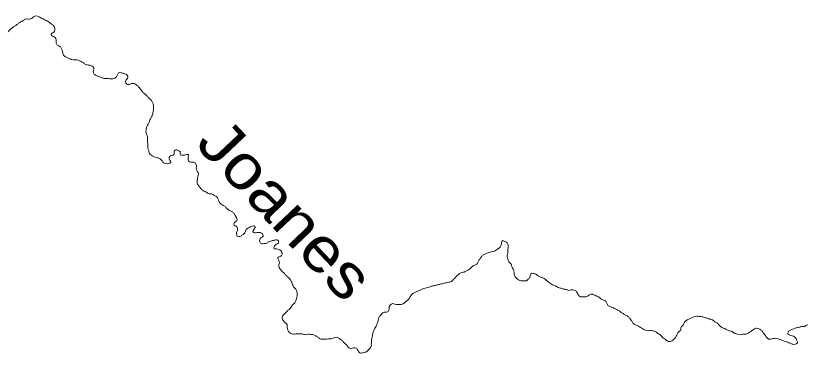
# Model space of a CAD drawing. Extents: x 854879 to 917879, y 8541948 to 8631048.
# Drawn here: x 880862 to 887947, y 8603519 to 8606565 of the extents above; entities that cross this region are included whole.
import ezdxf

# ---------------------------------------------------------------- set-up
doc = ezdxf.new("R2010")
doc.units = 0
doc.header["$LTSCALE"] = 160
doc.layers.add('1', color=7, linetype='Continuous', lineweight=13)
doc.layers.add('3', color=7, linetype='Continuous', lineweight=13)

msp = doc.modelspace()

# ---------------------------------------------------------------- linework, layer by layer
at = {"layer": '3'}
for points in [[(880861.8, 8606477.6), (880882.8, 8606492), (880906.5, 8606508.9), (880929.9, 8606520.7), (880950.9, 8606535.1), (880973.8, 8606534.1), (881012.6, 8606545.3), (881033.7, 8606562.2), (881059.1, 8606561.2), (881086.6, 8606547.3), (881109.1, 8606536.2), (881129.1, 8606525.2), (881149.1, 8606516.7), (881176.3, 8606495.2), (881196.2, 8606481.6), (881213.2, 8606460.6), (881214.7, 8606435), (881203.7, 8606415.1), (881185.4, 8606405.6), (881187.1, 8606385.2), (881209.6, 8606374.1), (881224.3, 8606358.2), (881228.4, 8606335.1), (881232.3, 8606304.3), (881259.7, 8606287.9), (881276.7, 8606266.8), (881285.8, 8606241), (881289.8, 8606215.3), (881314.5, 8606193.9), (881339.5, 8606182.7), (881369.6, 8606168.7), (881389.9, 8606167.9), (881425.5, 8606163.9), (881453.1, 8606152.5), (881473, 8606141.5), (881492.8, 8606125.4), (881523.1, 8606119.1), (881553.4, 8606110.2), (881568, 8606094.3), (881564.6, 8606071.5), (881563.7, 8606051.1), (881583.3, 8606029.9), (881605.8, 8606018.8), (881635.9, 8606007.4), (881661.1, 8605998.7), (881684, 8605997.8), (881709.4, 8605996.7), (881729.8, 8605995.8), (881763.4, 8606007.2), (881776.9, 8606024.5), (881790.7, 8606049.4), (881813.7, 8606051), (881838.9, 8606042.3), (881868.9, 8606028.3), (881873.2, 8606007.8), (881856.7, 8605980.4), (881855.9, 8605960.1), (881870.6, 8605944.2), (881896.2, 8605948.2), (881919.5, 8605954.9), (881944.6, 8605946.2), (881961.9, 8605932.8), (881979, 8605914.2), (881993.6, 8605895.8), (882005.6, 8605877.4), (882025.3, 8605861.3), (882045, 8605842.7), (882064.5, 8605821.5), (882081.7, 8605805.5), (882098.6, 8605781.9), (882105.2, 8605756.1), (882106.6, 8605728), (882103, 8605702.7), (882099.4, 8605677.4), (882085.4, 8605647.4), (882074.3, 8605624.9), (882063, 8605597.3), (882051.9, 8605577.4), (882043.4, 8605554.8), (882039.9, 8605532.1), (882038.8, 8605506.6), (882048.2, 8605485.8), (882052.2, 8605460.2), (882051.3, 8605437.3), (882055.2, 8605409.1), (882056.3, 8605373.4), (882062.8, 8605345.1), (882069.5, 8605321.9), (882086.7, 8605305.9), (882111.7, 8605292.1), (882134.4, 8605286.1)], [(880861.8, 8606477.6), (880882.8, 8606492), (880906.5, 8606508.9), (880929.9, 8606520.7), (880950.9, 8606535.1), (880973.8, 8606534.1), (881012.6, 8606545.3), (881033.7, 8606562.2), (881059.1, 8606561.2), (881086.6, 8606547.3), (881109.1, 8606536.2), (881129.1, 8606525.2), (881149.1, 8606516.7), (881176.3, 8606495.2), (881196.2, 8606481.6), (881213.2, 8606460.6), (881214.7, 8606435), (881203.7, 8606415.1), (881185.4, 8606405.6), (881187.1, 8606385.2), (881209.6, 8606374.1), (881224.3, 8606358.2), (881228.4, 8606335.1), (881232.3, 8606304.3), (881259.7, 8606287.9), (881276.7, 8606266.8), (881285.8, 8606241), (881289.8, 8606215.3), (881314.5, 8606193.9), (881339.5, 8606182.7), (881369.6, 8606168.7), (881389.9, 8606167.9), (881425.5, 8606163.9), (881453.1, 8606152.5), (881473, 8606141.5), (881492.8, 8606125.4), (881523.1, 8606119.1), (881553.4, 8606110.2), (881568, 8606094.3), (881564.6, 8606071.5), (881563.7, 8606051.1), (881583.3, 8606029.9), (881605.8, 8606018.8), (881635.9, 8606007.4), (881661.1, 8605998.7), (881684, 8605997.8), (881709.4, 8605996.7), (881729.8, 8605995.8), (881763.4, 8606007.2), (881776.9, 8606024.5), (881790.7, 8606049.4), (881813.7, 8606051), (881838.9, 8606042.3), (881868.9, 8606028.3), (881873.2, 8606007.8), (881856.7, 8605980.4), (881855.9, 8605960.1), (881870.6, 8605944.2), (881896.2, 8605948.2), (881919.5, 8605954.9), (881944.6, 8605946.2), (881961.9, 8605932.8), (881979, 8605914.2), (881993.6, 8605895.8), (882005.6, 8605877.4), (882025.3, 8605861.3), (882045, 8605842.7), (882064.5, 8605821.5), (882081.7, 8605805.5), (882098.6, 8605781.9), (882105.2, 8605756.1), (882106.6, 8605728), (882103, 8605702.7), (882099.4, 8605677.4), (882085.4, 8605647.4), (882074.3, 8605624.9), (882063, 8605597.3), (882051.9, 8605577.4), (882043.4, 8605554.8), (882039.9, 8605532.1), (882038.8, 8605506.6), (882048.2, 8605485.8), (882052.2, 8605460.2), (882051.3, 8605437.3), (882055.2, 8605409.1), (882056.3, 8605373.4), (882062.8, 8605345.1), (882069.5, 8605321.9), (882086.7, 8605305.9), (882111.7, 8605292.1), (882134.4, 8605286.1)], [(880371.3, 8606429.1), (880426.5, 8606437), (880445.3, 8606459.2), (880461.5, 8606481.4), (880482.6, 8606498.4), (880508.7, 8606512.6), (880532.1, 8606524.4), (880563.3, 8606538.4), (880583.6, 8606535), (880603.6, 8606526.5), (880623.4, 8606510.4), (880645.8, 8606496.8), (880662.7, 8606473.1), (880679.7, 8606452), (880691.5, 8606428.6), (880708.2, 8606402.4), (880730.5, 8606386.2), (880761.4, 8606392.6), (880780, 8606409.7), (880795.9, 8606424.3), (880814.5, 8606443.9), (880838.3, 8606463.3), (880861.8, 8606477.6)], [(880371.3, 8606429.1), (880426.5, 8606437), (880445.3, 8606459.2), (880461.5, 8606481.4), (880482.6, 8606498.4), (880508.7, 8606512.6), (880532.1, 8606524.4), (880563.3, 8606538.4), (880583.6, 8606535), (880603.6, 8606526.5), (880623.4, 8606510.4), (880645.8, 8606496.8), (880662.7, 8606473.1), (880679.7, 8606452), (880691.5, 8606428.6), (880708.2, 8606402.4), (880730.5, 8606386.2), (880761.4, 8606392.6), (880780, 8606409.7), (880795.9, 8606424.3), (880814.5, 8606443.9), (880838.3, 8606463.3), (880861.8, 8606477.6)], [(882134.4, 8605286.1), (882159.5, 8605277.4), (882179.3, 8605261.3), (882196.2, 8605237.7), (882216.3, 8605231.8), (882241.8, 8605230.7), (882262.7, 8605242.6), (882250.9, 8605266), (882252.1, 8605294), (882272.8, 8605303.3), (882291.1, 8605312.7), (882292, 8605335.6), (882308.1, 8605355.3), (882328.3, 8605349.4), (882348.2, 8605335.9), (882347.3, 8605315.5), (882375, 8605306.7), (882398.2, 8605310.9), (882423.6, 8605309.8), (882420.2, 8605289.6), (882419.3, 8605266.7), (882431.2, 8605245.8), (882456.7, 8605244.7), (882479.4, 8605238.7), (882493.6, 8605212.6), (882492.7, 8605189.8), (882496.9, 8605169.2), (882511.3, 8605145.7), (882510.3, 8605122.8), (882504.3, 8605100.1), (882500.8, 8605077.3), (882499.8, 8605051.9), (882514.2, 8605030.9), (882533.7, 8605007.2), (882555.7, 8604985.9), (882575.8, 8604977.4), (882608.2, 8604958.2), (882628.6, 8604957.4), (882653.5, 8604943.6), (882676, 8604932.5), (882688, 8604914.1), (882697.2, 8604890.8), (882709.2, 8604872.5), (882726.6, 8604859), (882746.5, 8604848), (882766.2, 8604829.4), (882788.3, 8604810.6), (882810.8, 8604799.5), (882830.6, 8604783.4), (882845, 8604762.4), (882854.5, 8604744.2), (882858.5, 8604716), (882834.7, 8604696.6), (882833.9, 8604676.2), (882853.8, 8604665.2), (882865.5, 8604639.3), (882859.5, 8604616.6), (882856.1, 8604596.3), (882867.9, 8604572.9), (882893.6, 8604577), (882914.6, 8604591.4), (882933.2, 8604611), (882939.2, 8604631.1), (882962.9, 8604650.5), (882986.3, 8604662.3), (883007, 8604669.1), (883024.4, 8604658.2), (883013.3, 8604635.7), (883002.4, 8604618.3), (883019.7, 8604604.9), (883040.3, 8604609.1), (883070.8, 8604607.8), (883090.8, 8604596.8), (883095.1, 8604576.3), (883076.6, 8604561.8), (883065.7, 8604544.4), (883064.9, 8604524), (883084.6, 8604507.9), (883105.1, 8604509.6), (883128.2, 8604513.8), (883151.8, 8604528.1), (883175, 8604534.8), (883203.3, 8604541.2), (883233.7, 8604534.9), (883235.4, 8604514.4), (883214.5, 8604502.5), (883198.5, 8604485.4), (883195, 8604462.6), (883217.9, 8604461.6), (883240.6, 8604455.6), (883260.5, 8604442)], [(882134.4, 8605286.1), (882159.5, 8605277.4), (882179.3, 8605261.3), (882196.2, 8605237.7), (882216.3, 8605231.8), (882241.8, 8605230.7), (882262.7, 8605242.6), (882250.9, 8605266), (882252.1, 8605294), (882272.8, 8605303.3), (882291.1, 8605312.7), (882292, 8605335.6), (882308.1, 8605355.3), (882328.3, 8605349.4), (882348.2, 8605335.9), (882347.3, 8605315.5), (882375, 8605306.7), (882398.2, 8605310.9), (882423.6, 8605309.8), (882420.2, 8605289.6), (882419.3, 8605266.7), (882431.2, 8605245.8), (882456.7, 8605244.7), (882479.4, 8605238.7), (882493.6, 8605212.6), (882492.7, 8605189.8), (882496.9, 8605169.2), (882511.3, 8605145.7), (882510.3, 8605122.8), (882504.3, 8605100.1), (882500.8, 8605077.3), (882499.8, 8605051.9), (882514.2, 8605030.9), (882533.7, 8605007.2), (882555.7, 8604985.9), (882575.8, 8604977.4), (882608.2, 8604958.2), (882628.6, 8604957.4), (882653.5, 8604943.6), (882676, 8604932.5), (882688, 8604914.1), (882697.2, 8604890.8), (882709.2, 8604872.5), (882726.6, 8604859), (882746.5, 8604848), (882766.2, 8604829.4), (882788.3, 8604810.6), (882810.8, 8604799.5), (882830.6, 8604783.4), (882845, 8604762.4), (882854.5, 8604744.2), (882858.5, 8604716), (882834.7, 8604696.6), (882833.9, 8604676.2), (882853.8, 8604665.2), (882865.5, 8604639.3), (882859.5, 8604616.6), (882856.1, 8604596.3), (882867.9, 8604572.9), (882893.6, 8604577), (882914.6, 8604591.4), (882933.2, 8604611), (882939.2, 8604631.1), (882962.9, 8604650.5), (882986.3, 8604662.3), (883007, 8604669.1), (883024.4, 8604658.2), (883013.3, 8604635.7), (883002.4, 8604618.3), (883019.7, 8604604.9), (883040.3, 8604609.1), (883070.8, 8604607.8), (883090.8, 8604596.8), (883095.1, 8604576.3), (883076.6, 8604561.8), (883065.7, 8604544.4), (883064.9, 8604524), (883084.6, 8604507.9), (883105.1, 8604509.6), (883128.2, 8604513.8), (883151.8, 8604528.1), (883175, 8604534.8), (883203.3, 8604541.2), (883233.7, 8604534.9), (883235.4, 8604514.4), (883214.5, 8604502.5), (883198.5, 8604485.4), (883195, 8604462.6), (883217.9, 8604461.6), (883240.6, 8604455.6), (883260.5, 8604442)], [(884400.4, 8603997.4), (884413.8, 8604014.7), (884430.2, 8604039.5), (884448.8, 8604059.1), (884472.3, 8604070.9), (884498.2, 8604082.6), (884519, 8604091.9), (884545, 8604103.6), (884570.8, 8604110.1), (884594, 8604116.8), (884622.5, 8604125.8), (884650.8, 8604132.3), (884679.1, 8604138.8), (884712.6, 8604147.6), (884751.3, 8604156.2), (884771.8, 8604160.4), (884792.4, 8604164.7), (884813.6, 8604184.2), (884834.9, 8604206.2), (884856.2, 8604228.3), (884882.5, 8604245), (884921.2, 8604256.2), (884944.7, 8604270.5), (884963.1, 8604282.5), (884981.6, 8604299.5), (885007.7, 8604313.7), (885028.7, 8604328.2), (885039.8, 8604350.6), (885056.2, 8604375.4), (885072.3, 8604395.1), (885090.8, 8604412.2), (885116.7, 8604421.3), (885137.4, 8604428.1), (885158.1, 8604434.9), (885183.9, 8604441.5), (885202.2, 8604453.5), (885225.8, 8604467.8), (885241.9, 8604487.5), (885247.8, 8604507.6), (885256.6, 8604535.3), (885279.3, 8604529.3), (885304, 8604510.4), (885308.1, 8604484.8), (885306.9, 8604456.8), (885306, 8604433.9), (885302.6, 8604413.7), (885299.2, 8604393.4), (885305.8, 8604367.7), (885320, 8604339), (885334.6, 8604323.2), (885343.8, 8604297.3), (885353.2, 8604279.1), (885362.2, 8604250.7), (885366.2, 8604222.5), (885383, 8604196.3), (885402.8, 8604182.7), (885422.9, 8604174.3), (885443.3, 8604173.4), (885468.7, 8604172.4), (885489.7, 8604186.8), (885505.8, 8604206.5), (885512.2, 8604236.8), (885537.9, 8604240.8), (885562.9, 8604229.6), (885585.3, 8604216), (885610.4, 8604204.7), (885632.9, 8604193.6), (885650.3, 8604182.7), (885672.4, 8604161.4), (885689.8, 8604150.5), (885709.6, 8604136.9), (885729.8, 8604131), (885759.7, 8604114.5), (885779.9, 8604108.5), (885805, 8604099.9), (885835.4, 8604093.5), (885858, 8604084.9), (885878.7, 8604091.7), (885909, 8604085.4), (885931.3, 8604069.2), (885940.7, 8604048.4), (885962.9, 8604029.6), (885983.2, 8604028.8), (886019.1, 8604032.4), (886042.7, 8604046.7), (886065.9, 8604053.4), (886091, 8604044.7), (886111, 8604033.7), (886131.1, 8604025.2), (886148.2, 8604009.2), (886180.3, 8603996.9)], [(884400.4, 8603997.4), (884413.8, 8604014.7), (884430.2, 8604039.5), (884448.8, 8604059.1), (884472.3, 8604070.9), (884498.2, 8604082.6), (884519, 8604091.9), (884545, 8604103.6), (884570.8, 8604110.1), (884594, 8604116.8), (884622.5, 8604125.8), (884650.8, 8604132.3), (884679.1, 8604138.8), (884712.6, 8604147.6), (884751.3, 8604156.2), (884771.8, 8604160.4), (884792.4, 8604164.7), (884813.6, 8604184.2), (884834.9, 8604206.2), (884856.2, 8604228.3), (884882.5, 8604245), (884921.2, 8604256.2), (884944.7, 8604270.5), (884963.1, 8604282.5), (884981.6, 8604299.5), (885007.7, 8604313.7), (885028.7, 8604328.2), (885039.8, 8604350.6), (885056.2, 8604375.4), (885072.3, 8604395.1), (885090.8, 8604412.2), (885116.7, 8604421.3), (885137.4, 8604428.1), (885158.1, 8604434.9), (885183.9, 8604441.5), (885202.2, 8604453.5), (885225.8, 8604467.8), (885241.9, 8604487.5), (885247.8, 8604507.6), (885256.6, 8604535.3), (885279.3, 8604529.3), (885304, 8604510.4), (885308.1, 8604484.8), (885306.9, 8604456.8), (885306, 8604433.9), (885302.6, 8604413.7), (885299.2, 8604393.4), (885305.8, 8604367.7), (885320, 8604339), (885334.6, 8604323.2), (885343.8, 8604297.3), (885353.2, 8604279.1), (885362.2, 8604250.7), (885366.2, 8604222.5), (885383, 8604196.3), (885402.8, 8604182.7), (885422.9, 8604174.3), (885443.3, 8604173.4), (885468.7, 8604172.4), (885489.7, 8604186.8), (885505.8, 8604206.5), (885512.2, 8604236.8), (885537.9, 8604240.8), (885562.9, 8604229.6), (885585.3, 8604216), (885610.4, 8604204.7), (885632.9, 8604193.6), (885650.3, 8604182.7), (885672.4, 8604161.4), (885689.8, 8604150.5), (885709.6, 8604136.9), (885729.8, 8604131), (885759.7, 8604114.5), (885779.9, 8604108.5), (885805, 8604099.9), (885835.4, 8604093.5), (885858, 8604084.9), (885878.7, 8604091.7), (885909, 8604085.4), (885931.3, 8604069.2), (885940.7, 8604048.4), (885962.9, 8604029.6), (885983.2, 8604028.8), (886019.1, 8604032.4), (886042.7, 8604046.7), (886065.9, 8604053.4), (886091, 8604044.7), (886111, 8604033.7), (886131.1, 8604025.2), (886148.2, 8604009.2), (886180.3, 8603996.9)], [(883260.5, 8604442), (883267.3, 8604421.4), (883256.1, 8604396.4), (883230, 8604382.2), (883241.3, 8604348.6), (883240.4, 8604325.7), (883237, 8604305.4), (883246.4, 8604284.7), (883263.4, 8604263.6), (883280.6, 8604247.6), (883297.7, 8604229), (883317.3, 8604210.4), (883334.5, 8604194.4), (883348.8, 8604170.9), (883358.2, 8604150.1), (883367.4, 8604126.8), (883382, 8604108.3), (883396.4, 8604087.4), (883403, 8604061.6), (883402.1, 8604038.7), (883396, 8604013.5), (883390, 8603993.3), (883378.9, 8603970.9), (883357.7, 8603951.4), (883346.7, 8603931.4), (883320.2, 8603907.1), (883301.5, 8603887.4), (883280.3, 8603867.9), (883268.9, 8603837.8), (883278.1, 8603814.5), (883297.7, 8603793.3), (883312.2, 8603774.9), (883313.9, 8603754.4), (883318, 8603728.8), (883337.4, 8603705.1), (883354.8, 8603694.2), (883377.7, 8603693.2), (883403.3, 8603694.7), (883428.9, 8603696.2), (883449.2, 8603695.3), (883477, 8603686.6), (883502.6, 8603690.6), (883523, 8603689.8), (883553.5, 8603685.9), (883576, 8603674.8), (883595.7, 8603658.7), (883618.2, 8603647.6), (883648.8, 8603646.3), (883671.8, 8603647.9), (883697.4, 8603649.4), (883723, 8603653.4), (883743.8, 8603662.8), (883766.7, 8603661.8), (883791.7, 8603648.1), (883809, 8603634.6), (883826.1, 8603616.1), (883848.2, 8603594.8), (883867.6, 8603571), (883887.7, 8603562.6), (883913.5, 8603569.1), (883936.3, 8603565.7), (883953.3, 8603544.6), (883970.2, 8603523.5), (884000.9, 8603524.8), (884029.3, 8603533.8), (884053.2, 8603555.7), (884072.2, 8603583), (884073, 8603603.3), (884073.8, 8603623.7), (884074.7, 8603644), (884080.6, 8603664.1), (884084.1, 8603686.9), (884093, 8603717.1), (884104.3, 8603744.7), (884117.9, 8603764.5), (884126.7, 8603792.2), (884135.3, 8603817.3), (884141.5, 8603842.5), (884157.6, 8603862.2), (884171.1, 8603879.5), (884197.1, 8603891.2), (884220.1, 8603892.8), (884233.7, 8603915.1), (884234.8, 8603940.6), (884245.7, 8603958), (884276.7, 8603966.9), (884296.8, 8603960.9), (884322.3, 8603959.9), (884355.6, 8603963.6), (884376.6, 8603978), (884400.4, 8603997.4)], [(883260.5, 8604442), (883267.3, 8604421.4), (883256.1, 8604396.4), (883230, 8604382.2), (883241.3, 8604348.6), (883240.4, 8604325.7), (883237, 8604305.4), (883246.4, 8604284.7), (883263.4, 8604263.6), (883280.6, 8604247.6), (883297.7, 8604229), (883317.3, 8604210.4), (883334.5, 8604194.4), (883348.8, 8604170.9), (883358.2, 8604150.1), (883367.4, 8604126.8), (883382, 8604108.3), (883396.4, 8604087.4), (883403, 8604061.6), (883402.1, 8604038.7), (883396, 8604013.5), (883390, 8603993.3), (883378.9, 8603970.9), (883357.7, 8603951.4), (883346.7, 8603931.4), (883320.2, 8603907.1), (883301.5, 8603887.4), (883280.3, 8603867.9), (883268.9, 8603837.8), (883278.1, 8603814.5), (883297.7, 8603793.3), (883312.2, 8603774.9), (883313.9, 8603754.4), (883318, 8603728.8), (883337.4, 8603705.1), (883354.8, 8603694.2), (883377.7, 8603693.2), (883403.3, 8603694.7), (883428.9, 8603696.2), (883449.2, 8603695.3), (883477, 8603686.6), (883502.6, 8603690.6), (883523, 8603689.8), (883553.5, 8603685.9), (883576, 8603674.8), (883595.7, 8603658.7), (883618.2, 8603647.6), (883648.8, 8603646.3), (883671.8, 8603647.9), (883697.4, 8603649.4), (883723, 8603653.4), (883743.8, 8603662.8), (883766.7, 8603661.8), (883791.7, 8603648.1), (883809, 8603634.6), (883826.1, 8603616.1), (883848.2, 8603594.8), (883867.6, 8603571), (883887.7, 8603562.6), (883913.5, 8603569.1), (883936.3, 8603565.7), (883953.3, 8603544.6), (883970.2, 8603523.5), (884000.9, 8603524.8), (884029.3, 8603533.8), (884053.2, 8603555.7), (884072.2, 8603583), (884073, 8603603.3), (884073.8, 8603623.7), (884074.7, 8603644), (884080.6, 8603664.1), (884084.1, 8603686.9), (884093, 8603717.1), (884104.3, 8603744.7), (884117.9, 8603764.5), (884126.7, 8603792.2), (884135.3, 8603817.3), (884141.5, 8603842.5), (884157.6, 8603862.2), (884171.1, 8603879.5), (884197.1, 8603891.2), (884220.1, 8603892.8), (884233.7, 8603915.1), (884234.8, 8603940.6), (884245.7, 8603958), (884276.7, 8603966.9), (884296.8, 8603960.9), (884322.3, 8603959.9), (884355.6, 8603963.6), (884376.6, 8603978), (884400.4, 8603997.4)], [(887833.8, 8603621), (887853.8, 8603610), (887878.9, 8603601.3), (887899.3, 8603600.5), (887920.2, 8603612.4), (887916, 8603635.5), (887904.2, 8603658.9), (887884.4, 8603672.5), (887861.8, 8603681), (887834.2, 8603692.4), (887840.3, 8603717.6), (887863.9, 8603731.9), (887887.2, 8603741.1), (887913.1, 8603750.3), (887933.6, 8603752), (887959.5, 8603761.1), (887979.8, 8603760.2), (888003.3, 8603772), (888026.5, 8603778.7), (888047.4, 8603790.6), (888066, 8603807.6), (888087.1, 8603824.6), (888105.3, 8603834), (888126.3, 8603848.4), (888149.4, 8603852.6), (888165.3, 8603867.2), (888173.8, 8603887.2), (888196.9, 8603891.4), (888224.8, 8603887.7), (888244.9, 8603879.2), (888262.3, 8603868.3), (888277, 8603852.4), (888299.4, 8603838.8), (888324.7, 8603835.2), (888353.2, 8603844.2), (888366.8, 8603866.5), (888396.1, 8603895.9), (888422.3, 8603912.7), (888440.8, 8603929.7), (888452, 8603952.2), (888462.9, 8603969.6), (888466.5, 8603994.9), (888477.9, 8604025), (888496.8, 8604049.7), (888515.6, 8604074.4), (888541.5, 8604083.5), (888569.5, 8604082.4), (888592, 8604071.2), (888612.2, 8604065.3), (888629.4, 8604049.3), (888659.3, 8604032.8), (888676.5, 8604016.8), (888701.5, 8604003), (888718.9, 8603992.1), (888722.8, 8603963.9), (888724.6, 8603943.5), (888745.1, 8603947.7), (888768.6, 8603959.5), (888791.7, 8603963.6), (888814.7, 8603965.2), (888842.7, 8603964.1), (888863.1, 8603963.2), (888889, 8603972.3), (888907.5, 8603986.9), (888923.5, 8604004), (888941.9, 8604018.6), (888964.8, 8604017.6), (888987, 8603998.8), (889009.8, 8603995.4), (889035.5, 8603999.4), (889056.2, 8604006.2), (889082.3, 8604020.4), (889105.7, 8604032.2), (889127, 8604054.2), (889150.6, 8604068.5), (889172, 8604093.1), (889190.7, 8604112.7), (889204.1, 8604130), (889212.7, 8604152.6), (889231.5, 8604174.7), (889242.4, 8604192.1), (889258.6, 8604214.4), (889269.8, 8604239.4), (889281, 8604261.9), (889287, 8604284.6), (889298.1, 8604307), (889309.6, 8604337.1), (889323, 8604354.4), (889331.5, 8604374.4), (889342.8, 8604402), (889351.4, 8604424.6)], [(886180.3, 8603996.9), (886183.3, 8603992.5), (886200.3, 8603971.4), (886209.6, 8603950.6), (886232.1, 8603939.5), (886259.7, 8603928.2), (886289.8, 8603914.2), (886309.7, 8603903.2), (886334.5, 8603884.3), (886359.4, 8603870.6), (886384.3, 8603856.8), (886404, 8603838.1), (886420.9, 8603814.5), (886435.2, 8603791), (886457.6, 8603777.3), (886485.1, 8603763.4), (886505.1, 8603752.4), (886524.9, 8603738.9), (886557.5, 8603724.8), (886585.5, 8603723.6), (886613.5, 8603722.5), (886641.2, 8603713.7), (886668.5, 8603694.7), (886688.4, 8603681.2), (886702.9, 8603662.7), (886720.2, 8603649.3), (886737.5, 8603635.8), (886757.6, 8603627.3), (886785.8, 8603631.3), (886804.2, 8603645.8), (886820.3, 8603663), (886831.3, 8603682.9), (886839.8, 8603702.9), (886855.7, 8603717.6), (886869.1, 8603734.8), (886870, 8603755.2), (886888.5, 8603772.2), (886897.1, 8603794.8), (886913.1, 8603812), (886939.3, 8603828.7), (886965.3, 8603840.4), (886988.6, 8603849.6), (887011.8, 8603853.8), (887034.7, 8603852.8), (887060, 8603849.2), (887087.7, 8603840.4), (887108, 8603837.1), (887128.1, 8603828.6), (887153.2, 8603819.9), (887175.5, 8603803.7), (887197.9, 8603790), (887219.9, 8603766.2), (887244.7, 8603749.9), (887272.3, 8603738.5), (887297.3, 8603724.8), (887325.1, 8603718.5), (887349.9, 8603702.2), (887377.6, 8603693.4), (887402.9, 8603687.3), (887428.6, 8603691.3), (887456.7, 8603692.7), (887480.1, 8603704.5), (887498.5, 8603716.4), (887527.3, 8603735.6), (887550.7, 8603747.4), (887573.3, 8603738.8), (887598.3, 8603725.1), (887612.7, 8603704.1), (887627.3, 8603685.6), (887644.2, 8603662), (887666.5, 8603645.8), (887689.6, 8603649.9), (887710.2, 8603654.2), (887735.7, 8603653.1), (887755.8, 8603647.2), (887778.4, 8603638.6), (887811.1, 8603627.1), (887833.8, 8603621)], [(886180.3, 8603996.9), (886183.3, 8603992.5), (886200.3, 8603971.4), (886209.6, 8603950.6), (886232.1, 8603939.5), (886259.7, 8603928.2), (886289.8, 8603914.2), (886309.7, 8603903.2), (886334.5, 8603884.3), (886359.4, 8603870.6), (886384.3, 8603856.8), (886404, 8603838.1), (886420.9, 8603814.5), (886435.2, 8603791), (886457.6, 8603777.3), (886485.1, 8603763.4), (886505.1, 8603752.4), (886524.9, 8603738.9), (886557.5, 8603724.8), (886585.5, 8603723.6), (886613.5, 8603722.5), (886641.2, 8603713.7), (886668.5, 8603694.7), (886688.4, 8603681.2), (886702.9, 8603662.7), (886720.2, 8603649.3), (886737.5, 8603635.8), (886757.6, 8603627.3), (886785.8, 8603631.3), (886804.2, 8603645.8), (886820.3, 8603663), (886831.3, 8603682.9), (886839.8, 8603702.9), (886855.7, 8603717.6), (886869.1, 8603734.8), (886870, 8603755.2), (886888.5, 8603772.2), (886897.1, 8603794.8), (886913.1, 8603812), (886939.3, 8603828.7), (886965.3, 8603840.4), (886988.6, 8603849.6), (887011.8, 8603853.8), (887034.7, 8603852.8), (887060, 8603849.2), (887087.7, 8603840.4), (887108, 8603837.1), (887128.1, 8603828.6), (887153.2, 8603819.9), (887175.5, 8603803.7), (887197.9, 8603790), (887219.9, 8603766.2), (887244.7, 8603749.9), (887272.3, 8603738.5), (887297.3, 8603724.8), (887325.1, 8603718.5), (887349.9, 8603702.2), (887377.6, 8603693.4), (887402.9, 8603687.3), (887428.6, 8603691.3), (887456.7, 8603692.7), (887480.1, 8603704.5), (887498.5, 8603716.4), (887527.3, 8603735.6), (887550.7, 8603747.4), (887573.3, 8603738.8), (887598.3, 8603725.1), (887612.7, 8603704.1), (887627.3, 8603685.6), (887644.2, 8603662), (887666.5, 8603645.8), (887689.6, 8603649.9), (887710.2, 8603654.2), (887735.7, 8603653.1), (887755.8, 8603647.2), (887778.4, 8603638.6), (887811.1, 8603627.1), (887833.8, 8603621)]]:
    msp.add_spline(points, degree=3, dxfattribs=at)

# ---------------------------------------------------------------- texts
at = {"layer": '1', "width": 1.15}
msp.add_text('Joanes', height=400, rotation=313.428, dxfattribs=at).set_placement((882473.1, 8605400.5))

doc.saveas('drawing.dxf')
